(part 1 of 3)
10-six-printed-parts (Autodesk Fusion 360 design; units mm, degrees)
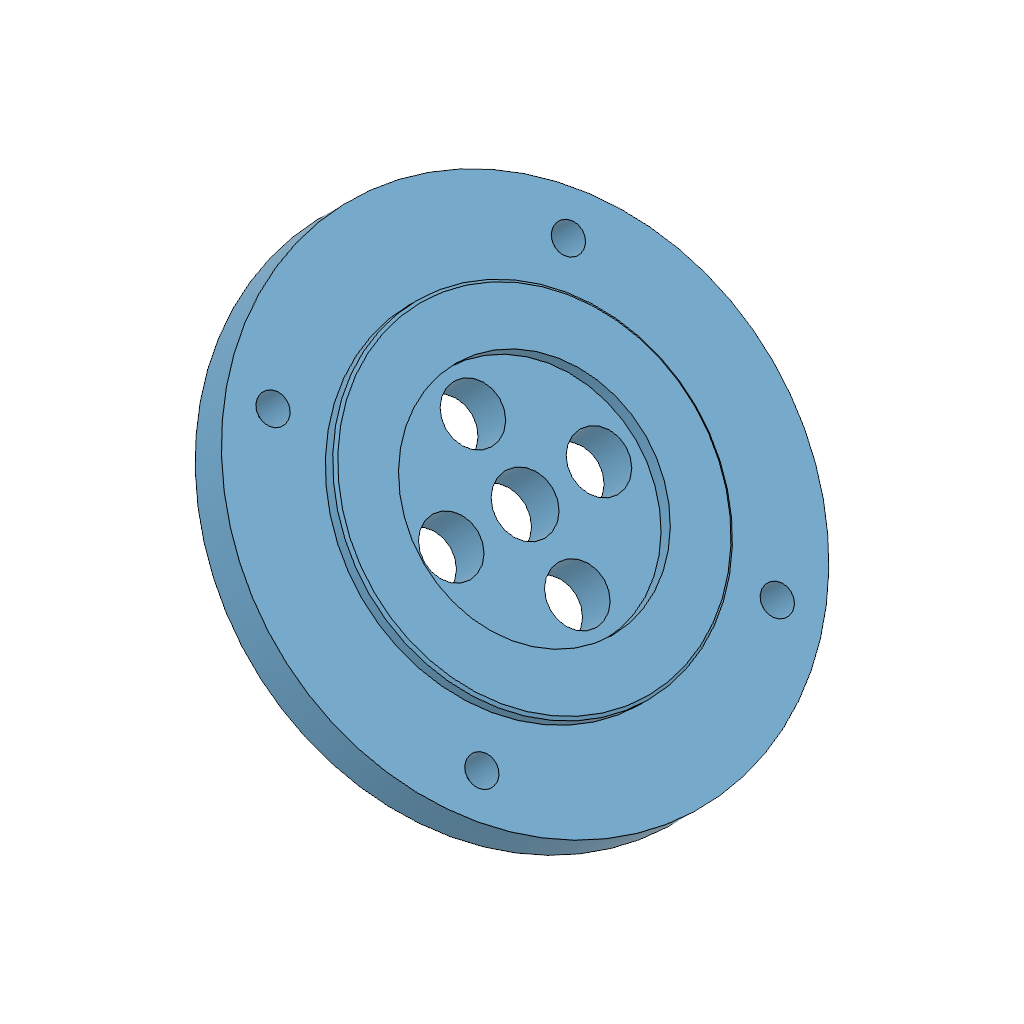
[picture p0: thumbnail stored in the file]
part number: 2026-11-02-20-17-55-344
part number: 2026-11-02-20-17-59-218
part number: 2026-11-02-20-17-59-224
part number: 2026-11-02-20-19-00-695
part number: 2026-11-02-20-19-03-009
part number: 2026-11-02-20-19-04-949
part number: 2026-11-02-20-19-06-912
parameter "bodyWidth" = 150 comment "Regular octagon across flats; corner diameter is larger."
parameter "bodyLength" = 260 comment "Overall straight length of the shared master blank."
parameter "splitAngle" = 45 comment "Keep this lesson angle at45 degrees."
parameter "faceGap" = 1 comment "Gap between the two printed joint faces."
parameter "wall" = 4.5 comment "Integrated shell and side brace radial thickness."
parameter "faceHalfWidth" = 31.066 (= "bodyWidth * ( sqrt(2) - 1 ) / 2") comment "Half-width of each outer planar facet."
parameter "memberWidth" = 8 comment "Nominal brace and corner chord width in a facet."
parameter "nodeHalfWidth" = 27.066 (= "faceHalfWidth - memberWidth / 2") comment "Chord centerlines measured from facet center."
parameter "jointNodeQ" = 7 comment "First truss skeleton row from the center joint plane."
parameter "endRim" = 10 comment "Uncut axial rim at each distant end."
parameter "endNodeX" = 124 (= "bodyLength / 2 - endRim + memberWidth / 2") comment "Last skeleton row before aperture inset."
parameter "apertureRadius" = 1.5 comment "Rounded internal corners at triangular openings."
parameter "spokeWidth" = 10 comment "Width of each deep bearing bulkhead spoke."
parameter "spokeDepth" = 18 comment "Bulkhead depth normal to the diagonal joint face."
parameter "carrierOD" = 52 comment "Outside of integrated A front bearing carrier."
parameter "rearCarrierClearance" = 46 comment "Internal carrier relief above front bearing shoulder."
parameter "tubeCornerChamfer" = 0.5 comment "Exposed outside octagon corner bevel."
parameter "tubeRimChamfer" = 0.3 comment "End rim and print-contact edge relief."
parameter "cordStation" = 125 (= "bodyLength / 2 - endRim / 2") comment "Load-test cord port center measured along body X."
parameter "bearingOD" = 22 comment "608 measured outside diameter."
parameter "bearingID" = 8 comment "608 bore."
parameter "bearingWidth" = 7 comment "608 width."
parameter "seatAllowance" = 0.2 comment "Trial DIAMETRAL clearance; choose with printed coupon."
parameter "seatDiameter" = 22.2 (= "bearingOD + seatAllowance") comment "Measured fit controls this."
parameter "coreOD" = 44 comment "Bearing holder outer diameter."
parameter "raceRelief" = 19.5 comment "Outer-ring shoulder opening; verify seals."
parameter "frontSeatDepth" = 7.1 comment "0.1 mm outer-ring axial allowance."
parameter "rearSeatDepth" = 7.2 comment "0.2 mm outer-ring axial float."
parameter "shoulder" = 3 comment "Backing behind each bearing seat."
parameter "supportSpacer" = 12 comment "Purchased metal M3 spacer length."
parameter "supportCircle" = 34 comment "Three M3 support bolts."
parameter "supportSpacerOD" = 6 comment "Purchased spacer outside diameter."
parameter "capThickness" = 3 comment "Both printed outer-ring retaining caps."
parameter "m3Clearance" = 3.3 comment "M3 through holes."
parameter "m4Clearance" = 4.3 comment "M4 through holes."
parameter "qFront" = 0.5 (= "faceGap / 2") comment "Front bearing starts at A mating face."
parameter "qFrontBack" = 10.6 (= "qFront + frontSeatDepth + shoulder") comment "End of integrated A holder."
parameter "qRearBase" = 22.6 (= "qFrontBack + supportSpacer") comment "Start of removable rear holder."
parameter "qRearBearing" = 25.6 (= "qRearBase + shoulder") comment "Rear bearing inner end."
parameter "qRearEnd" = 32.8 (= "qRearBearing + rearSeatDepth") comment "Rear holder outer end."
parameter "bearingSpacing" = 25.1 (= "qRearBearing - qFront") comment "Derived support-center spacing, not a bearing rating."
parameter "mountOD" = 76 comment "B mount and F flange outside diameter."
parameter "mountCircle" = 64 comment "Four M4 attachment holes."
parameter "mountOpening" = 50.3 comment "B through opening."
parameter "hubFace" = -23 comment "Metal hub flat mounting face."
parameter "adapterThickness" = 6 comment "F flange and metal compression sleeve length."
parameter "pilotDiameter" = 50 comment "F shallow centering pilot."
parameter "pilotInside" = 34 comment "Clearance around metal hub."
parameter "pilotHeight" = 2 comment "Short pilot only."
parameter "hubHoleSpacing" = 16 comment "Metal Sonic hub square hole spacing."
parameter "sleeveOD" = 8 comment "M4 metal compression sleeves."
parameter "sleeveAllowance" = 0.2 comment "Trial DIAMETRAL sleeve clearance."
parameter "shaftClearance" = 8.5 comment "F clearance hole; not a bearing."
parameter "nutAF" = 7.2 comment "M4 nominal 7 AF nut trial pocket."
parameter "nutDepth" = 4 comment "Open front M4 nut pocket."
parameter "rootRadius" = 1 comment "Hub-to-wall blend."
parameter "entryChamfer" = 0.4 comment "Assembly lead-in."
parameter "bedRelief" = 0.3 comment "Bed-contact edge allowance."
sketch "01 Master Octagon" plane through (0, 0, 0) normal (1, 0, 0) x axis (0, 0, -1)
  line L1 (31.066, 75) -> (75, 31.066)
  line L2 (-31.066, 75) -> (31.066, 75)
  line L3 (-75, 31.066) -> (-31.066, 75)
  line L4 (-75, -31.066) -> (-75, 31.066)
  line L5 (-31.066, -75) -> (-75, -31.066)
  line L6 (31.066, -75) -> (-31.066, -75)
  line L7 (75, -31.066) -> (31.066, -75)
  line L8 (75, 31.066) -> (75, -31.066)
  point P1 (0, 0)
  point P10 (0, 0)
  point P3 (31.066, 75)
  point P8 (31.066, -75)
  coincident P1 P10
  horizontal L2
  dimension "d59" distance P3 P8 = 150 (= "bodyWidth")
extrude "Extrude1" new body sketch "01 Master Octagon" distance 260 (= "bodyLength")
work_plane "WorkPlane1" RotateAngle 45 (= "splitAngle") ExtraOffset 0
split "Split1"
offset_faces "OffsetFaces1" distance -0.5 (= "-faceGap / 2")
offset_faces "OffsetFaces2" distance -0.5 (= "-faceGap / 2")
component_from_bodies "Body->Comp1"
component_from_bodies "Body->Comp2"
shell "Shell1" innerThickness 4.5 (= "wall")
shell "Shell1" innerThickness 4.5 (= "wall")
work_plane "WorkPlane1" RotateAngle -90 ExtraOffset 0
work_plane "WorkPlane2" AlongDistance 75 (= "bodyWidth / 2") ExtraOffset 0
sketch "A Facet 0 Triangle 1" plane through (0, 75, 0) normal (0, 1, 0) x axis (1, 0, 0)
  line L1 (-65.1005, -27.066) -> (-65.1005, 27.066)
  line L2 (60.9665, 27.066) -> (-65.1005, -27.066)
  line L3 (-65.1005, 27.066) -> (60.9665, 27.066)
  line L4 (-61.1005, -20.9953) -> (-61.1005, 23.066)
  line L5 (41.513, 23.066) -> (-61.1005, -20.9953)
  line L6 (-61.1005, 23.066) -> (41.513, 23.066)
  point P1 (0, 0)
  point P2 (-65.1005, 27.066)
  point P3 (-65.1005, -27.066)
  point P4 (60.9665, 27.066)
  dimension "d72" distance P1 P2 = 65.1005 (= "Linear Dimension-2")
  dimension "d73" distance P1 P2 = 27.066 (= "Linear Dimension-3")
  dimension "d74" distance P1 P3 = 65.1005 (= "Linear Dimension-4")
  dimension "d75" distance P1 P3 = 27.066 (= "Linear Dimension-5")
  dimension "d76" distance P1 P4 = 60.9665 (= "Linear Dimension-6")
  dimension "d77" distance P1 P4 = 27.066 (= "Linear Dimension-7")
  dimension "d78" = -4 (= "-memberWidth / 2")
extrude "Extrude1" cut sketch "A Facet 0 Triangle 1" profile of L5 L6 L4 against normal blind 4.7 (magnitude of "-( wall + 0.2 mm )")
sketch "A Facet 0 Triangle 2" plane through (0, 75, 0) normal (0, 1, 0) x axis (1, 0, 0)
  line L1 (60.9665, 27.066) -> (-65.1005, -27.066)
  line L2 (92.4832, -27.066) -> (60.9665, 27.066)
  line L3 (-65.1005, -27.066) -> (92.4832, -27.066)
  line L4 (59.2912, 21.9935) -> (-45.647, -23.066)
  line L5 (85.5258, -23.066) -> (59.2912, 21.9935)
  line L6 (-45.647, -23.066) -> (85.5258, -23.066)
  point P1 (0, 0)
  point P2 (-65.1005, -27.066)
  point P3 (60.9665, 27.066)
  point P4 (92.4832, -27.066)
  dimension "d81" distance P1 P2 = 65.1005 (= "Linear Dimension-2")
  dimension "d82" distance P1 P2 = 27.066 (= "Linear Dimension-3")
  dimension "d83" distance P1 P3 = 60.9665 (= "Linear Dimension-4")
  dimension "d84" distance P1 P3 = 27.066 (= "Linear Dimension-5")
  dimension "d85" distance P1 P4 = 92.4832 (= "Linear Dimension-6")
  dimension "d86" distance P1 P4 = 27.066 (= "Linear Dimension-7")
  dimension "d87" = 4 (= "memberWidth / 2")
extrude "Extrude2" cut sketch "A Facet 0 Triangle 2" profile of L5 L6 L4 against normal blind 4.7 (magnitude of "-( wall + 0.2 mm )")
sketch "A Facet 0 Triangle 3" plane through (0, 75, 0) normal (0, 1, 0) x axis (1, 0, 0)
  line L1 (92.4832, -27.066) -> (60.9665, 27.066)
  line L2 (124, 27.066) -> (92.4832, -27.066)
  line L3 (60.9665, 27.066) -> (124, 27.066)
  line L4 (92.4832, -19.1161) -> (67.924, 23.066)
  line L5 (117.0425, 23.066) -> (92.4832, -19.1161)
  line L6 (67.924, 23.066) -> (117.0425, 23.066)
  point P1 (0, 0)
  point P2 (60.9665, 27.066)
  point P3 (92.4832, -27.066)
  point P4 (124, 27.066)
  dimension "d90" distance P1 P2 = 60.9665 (= "Linear Dimension-2")
  dimension "d91" distance P1 P2 = 27.066 (= "Linear Dimension-3")
  dimension "d92" distance P1 P3 = 92.4832 (= "Linear Dimension-4")
  dimension "d93" distance P1 P3 = 27.066 (= "Linear Dimension-5")
  dimension "d94" distance P1 P4 = 124 (= "Linear Dimension-6")
  dimension "d95" distance P1 P4 = 27.066 (= "Linear Dimension-7")
  dimension "d96" = -4 (= "-memberWidth / 2")
extrude "Extrude3" cut sketch "A Facet 0 Triangle 3" profile of L5 L6 L4 against normal blind 4.7 (magnitude of "-( wall + 0.2 mm )")
sketch "A Facet 0 Triangle 4" plane through (0, 75, 0) normal (0, 1, 0) x axis (1, 0, 0)
  line L1 (124, 27.066) -> (92.4832, -27.066)
  line L2 (124, -27.066) -> (124, 27.066)
  line L3 (92.4832, -27.066) -> (124, -27.066)
  line L4 (120, 12.2459) -> (99.4407, -23.066)
  line L5 (120, -23.066) -> (120, 12.2459)
  line L6 (99.4407, -23.066) -> (120, -23.066)
  point P1 (0, 0)
  point P2 (92.4832, -27.066)
  point P3 (124, 27.066)
  point P4 (124, -27.066)
  dimension "d99" distance P1 P2 = 92.4832 (= "Linear Dimension-2")
  dimension "d100" distance P1 P2 = 27.066 (= "Linear Dimension-3")
  dimension "d101" distance P1 P3 = 124 (= "Linear Dimension-4")
  dimension "d102" distance P1 P3 = 27.066 (= "Linear Dimension-5")
  dimension "d103" distance P1 P4 = 124 (= "Linear Dimension-6")
  dimension "d104" distance P1 P4 = 27.066 (= "Linear Dimension-7")
  dimension "d105" = 4 (= "memberWidth / 2")
extrude "Extrude4" cut sketch "A Facet 0 Triangle 4" profile of L5 L6 L4 against normal blind 4.7 (magnitude of "-( wall + 0.2 mm )")
fillet "Fillet1" radius 1.5 (= "apertureRadius")
work_plane "WorkPlane3" RotateAngle -45 ExtraOffset 0
work_plane "WorkPlane4" AlongDistance 75 (= "bodyWidth / 2") ExtraOffset 0
sketch "A Facet 45 Triangle 1" plane through (0, 53.033, 53.033) normal (0, 0.7071, 0.7071) x axis (1, 0, 0)
  line L1 (-23.9949, -27.066) -> (-62.2721, 27.066)
  line L2 (-0.1814, 27.066) -> (-23.9949, -27.066)
  line L3 (-62.2721, 27.066) -> (-0.1814, 27.066)
  line L4 (-24.81, -18.9852) -> (-54.5447, 23.066)
  line L5 (-6.311, 23.066) -> (-24.81, -18.9852)
  line L6 (-54.5447, 23.066) -> (-6.311, 23.066)
  point P1 (0, 0)
  point P2 (-62.2721, 27.066)
  point P3 (-23.9949, -27.066)
  point P4 (-0.1814, 27.066)
  dimension "d114" distance P1 P2 = 62.2721 (= "Linear Dimension-2")
  dimension "d115" distance P1 P2 = 27.066 (= "Linear Dimension-3")
  dimension "d116" distance P1 P3 = 23.9949 (= "Linear Dimension-4")
  dimension "d117" distance P1 P3 = 27.066 (= "Linear Dimension-5")
  dimension "d118" distance P1 P4 = 0.1814 (= "Linear Dimension-6")
  dimension "d119" distance P1 P4 = 27.066 (= "Linear Dimension-7")
  dimension "d120" = -4 (= "-memberWidth / 2")
extrude "Extrude5" cut sketch "A Facet 45 Triangle 1" profile of L5 L6 L4 against normal blind 4.7 (magnitude of "-( wall + 0.2 mm )")
sketch "A Facet 45 Triangle 2" plane through (0, 53.033, 53.033) normal (0, 0.7071, 0.7071) x axis (1, 0, 0)
  line L1 (-0.1814, 27.066) -> (-23.9949, -27.066)
  line L2 (74.6684, -27.066) -> (-0.1814, 27.066)
  line L3 (-23.9949, -27.066) -> (74.6684, -27.066)
  line L4 (1.4863, 20.9235) -> (-17.8653, -23.066)
  line L5 (62.3117, -23.066) -> (1.4863, 20.9235)
  line L6 (-17.8653, -23.066) -> (62.3117, -23.066)
  point P1 (0, 0)
  point P2 (-23.9949, -27.066)
  point P3 (-0.1814, 27.066)
  point P4 (74.6684, -27.066)
  dimension "d123" distance P1 P2 = 23.9949 (= "Linear Dimension-2")
  dimension "d124" distance P1 P2 = 27.066 (= "Linear Dimension-3")
  dimension "d125" distance P1 P3 = 0.1814 (= "Linear Dimension-4")
  dimension "d126" distance P1 P3 = 27.066 (= "Linear Dimension-5")
  dimension "d127" distance P1 P4 = 74.6684 (= "Linear Dimension-6")
  dimension "d128" distance P1 P4 = 27.066 (= "Linear Dimension-7")
  dimension "d129" = 4 (= "memberWidth / 2")
extrude "Extrude6" cut sketch "A Facet 45 Triangle 2" profile of L5 L6 L4 against normal blind 4.7 (magnitude of "-( wall + 0.2 mm )")
sketch "A Facet 45 Triangle 3" plane through (0, 53.033, 53.033) normal (0, 0.7071, 0.7071) x axis (1, 0, 0)
  line L1 (74.6684, -27.066) -> (-0.1814, 27.066)
  line L2 (124, 27.066) -> (74.6684, -27.066)
  line L3 (-0.1814, 27.066) -> (124, 27.066)
  line L4 (74.1179, -21.7315) -> (12.1753, 23.066)
  line L5 (114.9429, 23.066) -> (74.1179, -21.7315)
  line L6 (12.1753, 23.066) -> (114.9429, 23.066)
  point P1 (0, 0)
  point P2 (-0.1814, 27.066)
  point P3 (74.6684, -27.066)
  point P4 (124, 27.066)
  dimension "d132" distance P1 P2 = 0.1814 (= "Linear Dimension-2")
  dimension "d133" distance P1 P2 = 27.066 (= "Linear Dimension-3")
  dimension "d134" distance P1 P3 = 74.6684 (= "Linear Dimension-4")
  dimension "d135" distance P1 P3 = 27.066 (= "Linear Dimension-5")
  dimension "d136" distance P1 P4 = 124 (= "Linear Dimension-6")
  dimension "d137" distance P1 P4 = 27.066 (= "Linear Dimension-7")
  dimension "d138" = -4 (= "-memberWidth / 2")
extrude "Extrude7" cut sketch "A Facet 45 Triangle 3" profile of L5 L6 L4 against normal blind 4.7 (magnitude of "-( wall + 0.2 mm )")
sketch "A Facet 45 Triangle 4" plane through (0, 53.033, 53.033) normal (0, 0.7071, 0.7071) x axis (1, 0, 0)
  line L1 (124, 27.066) -> (74.6684, -27.066)
  line L2 (124, -27.066) -> (124, 27.066)
  line L3 (74.6684, -27.066) -> (124, -27.066)
  line L4 (120, 16.7383) -> (83.7255, -23.066)
  line L5 (120, -23.066) -> (120, 16.7383)
  line L6 (83.7255, -23.066) -> (120, -23.066)
  point P1 (0, 0)
  point P2 (74.6684, -27.066)
  point P3 (124, 27.066)
  point P4 (124, -27.066)
  dimension "d141" distance P1 P2 = 74.6684 (= "Linear Dimension-2")
  dimension "d142" distance P1 P2 = 27.066 (= "Linear Dimension-3")
  dimension "d143" distance P1 P3 = 124 (= "Linear Dimension-4")
  dimension "d144" distance P1 P3 = 27.066 (= "Linear Dimension-5")
  dimension "d145" distance P1 P4 = 124 (= "Linear Dimension-6")
  dimension "d146" distance P1 P4 = 27.066 (= "Linear Dimension-7")
  dimension "d147" = 4 (= "memberWidth / 2")
extrude "Extrude8" cut sketch "A Facet 45 Triangle 4" profile of L5 L6 L4 against normal blind 4.7 (magnitude of "-( wall + 0.2 mm )")
fillet "Fillet2" radius 1.5 (= "apertureRadius")
work_plane "WorkPlane5" RotateAngle 0 ExtraOffset 0
work_plane "WorkPlane6" AlongDistance 75 (= "bodyWidth / 2") ExtraOffset 0
sketch "A Facet 90 Triangle 1" plane through (0, 0, 75) normal (0, 0, 1) x axis (1, 0, 0)
  line L1 (36.9655, -27.066) -> (-17.1665, 27.066)
  line L2 (53.4167, 27.066) -> (36.9655, -27.066)
  line L3 (-17.1665, 27.066) -> (53.4167, 27.066)
  line L4 (35.0777, -19.5214) -> (-7.5097, 23.066)
  line L5 (48.0205, 23.066) -> (35.0777, -19.5214)
  line L6 (-7.5097, 23.066) -> (48.0205, 23.066)
  point P1 (0, 0)
  point P2 (-17.1665, 27.066)
  point P3 (36.9655, -27.066)
  point P4 (53.4167, 27.066)
  dimension "d156" distance P1 P2 = 17.1665 (= "Linear Dimension-2")
  dimension "d157" distance P1 P2 = 27.066 (= "Linear Dimension-3")
  dimension "d158" distance P1 P3 = 36.9655 (= "Linear Dimension-4")
  dimension "d159" distance P1 P3 = 27.066 (= "Linear Dimension-5")
  dimension "d160" distance P1 P4 = 53.4167 (= "Linear Dimension-6")
  dimension "d161" distance P1 P4 = 27.066 (= "Linear Dimension-7")
  dimension "d162" = -4 (= "-memberWidth / 2")
extrude "Extrude9" cut sketch "A Facet 90 Triangle 1" profile of L5 L6 L4 against normal blind 4.7 (magnitude of "-( wall + 0.2 mm )")
sketch "A Facet 90 Triangle 2" plane through (0, 0, 75) normal (0, 0, 1) x axis (1, 0, 0)
  line L1 (53.4167, 27.066) -> (36.9655, -27.066)
  line L2 (124, -27.066) -> (53.4167, 27.066)
  line L3 (36.9655, -27.066) -> (124, -27.066)
  line L4 (55.5648, 20.3777) -> (42.3618, -23.066)
  line L5 (112.2115, -23.066) -> (55.5648, 20.3777)
  line L6 (42.3618, -23.066) -> (112.2115, -23.066)
  point P1 (0, 0)
  point P2 (36.9655, -27.066)
  point P3 (53.4167, 27.066)
  point P4 (124, -27.066)
  dimension "d165" distance P1 P2 = 36.9655 (= "Linear Dimension-2")
  dimension "d166" distance P1 P2 = 27.066 (= "Linear Dimension-3")
  dimension "d167" distance P1 P3 = 53.4167 (= "Linear Dimension-4")
  dimension "d168" distance P1 P3 = 27.066 (= "Linear Dimension-5")
  dimension "d169" distance P1 P4 = 124 (= "Linear Dimension-6")
  dimension "d170" distance P1 P4 = 27.066 (= "Linear Dimension-7")
  dimension "d171" = 4 (= "memberWidth / 2")
extrude "Extrude10" cut sketch "A Facet 90 Triangle 2" profile of L5 L6 L4 against normal blind 4.7 (magnitude of "-( wall + 0.2 mm )")
sketch "A Facet 90 Triangle 3" plane through (0, 0, 75) normal (0, 0, 1) x axis (1, 0, 0)
  line L1 (124, -27.066) -> (53.4167, 27.066)
  line L2 (124, 27.066) -> (124, -27.066)
  line L3 (53.4167, 27.066) -> (124, 27.066)
  line L4 (120, -18.9574) -> (65.2053, 23.066)
  line L5 (120, 23.066) -> (120, -18.9574)
  line L6 (65.2053, 23.066) -> (120, 23.066)
  point P1 (0, 0)
  point P2 (53.4167, 27.066)
  point P3 (124, -27.066)
  point P4 (124, 27.066)
  dimension "d174" distance P1 P2 = 53.4167 (= "Linear Dimension-2")
  dimension "d175" distance P1 P2 = 27.066 (= "Linear Dimension-3")
  dimension "d176" distance P1 P3 = 124 (= "Linear Dimension-4")
  dimension "d177" distance P1 P3 = 27.066 (= "Linear Dimension-5")
  dimension "d178" distance P1 P4 = 124 (= "Linear Dimension-6")
  dimension "d179" distance P1 P4 = 27.066 (= "Linear Dimension-7")
  dimension "d180" = -4 (= "-memberWidth / 2")
extrude "Extrude11" cut sketch "A Facet 90 Triangle 3" profile of L5 L6 L4 against normal blind 4.7 (magnitude of "-( wall + 0.2 mm )")
fillet "Fillet3" radius 1.5 (= "apertureRadius")
work_plane "WorkPlane7" RotateAngle 45 ExtraOffset 0
work_plane "WorkPlane8" AlongDistance 75 (= "bodyWidth / 2") ExtraOffset 0
sketch "A Facet 135 Triangle 1" plane through (0, -53.033, 53.033) normal (0, -0.7071, 0.7071) x axis (1, 0, 0)
  line L1 (82.0711, -27.066) -> (43.7939, 27.066)
  line L2 (124, 27.066) -> (82.0711, -27.066)
  line L3 (43.7939, 27.066) -> (124, 27.066)
  line L4 (82.2175, -20.3449) -> (51.5213, 23.066)
  line L5 (115.8422, 23.066) -> (82.2175, -20.3449)
  line L6 (51.5213, 23.066) -> (115.8422, 23.066)
  point P1 (0, 0)
  point P2 (43.7939, 27.066)
  point P3 (82.0711, -27.066)
  point P4 (124, 27.066)
  dimension "d189" distance P1 P2 = 43.7939 (= "Linear Dimension-2")
  dimension "d190" distance P1 P2 = 27.066 (= "Linear Dimension-3")
  dimension "d191" distance P1 P3 = 82.0711 (= "Linear Dimension-4")
  dimension "d192" distance P1 P3 = 27.066 (= "Linear Dimension-5")
  dimension "d193" distance P1 P4 = 124 (= "Linear Dimension-6")
  dimension "d194" distance P1 P4 = 27.066 (= "Linear Dimension-7")
  dimension "d195" = -4 (= "-memberWidth / 2")
extrude "Extrude12" cut sketch "A Facet 135 Triangle 1" profile of L5 L6 L4 against normal blind 4.7 (magnitude of "-( wall + 0.2 mm )")
sketch "A Facet 135 Triangle 2" plane through (0, -53.033, 53.033) normal (0, -0.7071, 0.7071) x axis (1, 0, 0)
  line L1 (124, 27.066) -> (82.0711, -27.066)
  line L2 (124, -27.066) -> (124, 27.066)
  line L3 (82.0711, -27.066) -> (124, -27.066)
  line L4 (120, 15.3697) -> (90.2289, -23.066)
  line L5 (120, -23.066) -> (120, 15.3697)
  line L6 (90.2289, -23.066) -> (120, -23.066)
  point P1 (0, 0)
  point P2 (82.0711, -27.066)
  point P3 (124, 27.066)
  point P4 (124, -27.066)
  dimension "d198" distance P1 P2 = 82.0711 (= "Linear Dimension-2")
  dimension "d199" distance P1 P2 = 27.066 (= "Linear Dimension-3")
  dimension "d200" distance P1 P3 = 124 (= "Linear Dimension-4")
  dimension "d201" distance P1 P3 = 27.066 (= "Linear Dimension-5")
  dimension "d202" distance P1 P4 = 124 (= "Linear Dimension-6")
  dimension "d203" distance P1 P4 = 27.066 (= "Linear Dimension-7")
  dimension "d204" = 4 (= "memberWidth / 2")
extrude "Extrude13" cut sketch "A Facet 135 Triangle 2" profile of L5 L6 L4 against normal blind 4.7 (magnitude of "-( wall + 0.2 mm )")
fillet "Fillet4" radius 1.5 (= "apertureRadius")
work_plane "WorkPlane9" RotateAngle 90 ExtraOffset 0
work_plane "WorkPlane10" AlongDistance 75 (= "bodyWidth / 2") ExtraOffset 0
sketch "A Facet 180 Triangle 1" plane through (0, -75, 0) normal (0, -1, 0) x axis (-1, 0, 0)
  line L1 (-84.8995, 27.066) -> (-84.8995, -27.066)
  line L2 (-124, -27.066) -> (-84.8995, 27.066)
  line L3 (-84.8995, -27.066) -> (-124, -27.066)
  line L4 (-88.8995, 14.697) -> (-88.8995, -23.066)
  line L5 (-116.1764, -23.066) -> (-88.8995, 14.697)
  line L6 (-88.8995, -23.066) -> (-116.1764, -23.066)
  point P1 (0, 0)
  point P2 (-84.8995, -27.066)
  point P3 (-84.8995, 27.066)
  point P4 (-124, -27.066)
  dimension "d213" distance P1 P2 = 84.8995 (= "Linear Dimension-2")
  dimension "d214" distance P1 P2 = 27.066 (= "Linear Dimension-3")
  dimension "d215" distance P1 P3 = 84.8995 (= "Linear Dimension-4")
  dimension "d216" distance P1 P3 = 27.066 (= "Linear Dimension-5")
  dimension "d217" distance P1 P4 = 124 (= "Linear Dimension-6")
  dimension "d218" distance P1 P4 = 27.066 (= "Linear Dimension-7")
  dimension "d219" = -4 (= "-memberWidth / 2")
extrude "Extrude14" cut sketch "A Facet 180 Triangle 1" profile of L5 L6 L4 against normal blind 4.7 (magnitude of "-( wall + 0.2 mm )")
sketch "A Facet 180 Triangle 2" plane through (0, -75, 0) normal (0, -1, 0) x axis (-1, 0, 0)
  line L1 (-124, -27.066) -> (-84.8995, 27.066)
  line L2 (-124, 27.066) -> (-124, -27.066)
  line L3 (-84.8995, 27.066) -> (-124, 27.066)
  line L4 (-120, -14.697) -> (-92.7231, 23.066)
  line L5 (-120, 23.066) -> (-120, -14.697)
  line L6 (-92.7231, 23.066) -> (-120, 23.066)
  point P1 (0, 0)
  point P2 (-84.8995, 27.066)
  point P3 (-124, -27.066)
  point P4 (-124, 27.066)
  dimension "d222" distance P1 P2 = 84.8995 (= "Linear Dimension-2")
  dimension "d223" distance P1 P2 = 27.066 (= "Linear Dimension-3")
  dimension "d224" distance P1 P3 = 124 (= "Linear Dimension-4")
  dimension "d225" distance P1 P3 = 27.066 (= "Linear Dimension-5")
  dimension "d226" distance P1 P4 = 124 (= "Linear Dimension-6")
  dimension "d227" distance P1 P4 = 27.066 (= "Linear Dimension-7")
  dimension "d228" = 4 (= "memberWidth / 2")
extrude "Extrude15" cut sketch "A Facet 180 Triangle 2" profile of L5 L6 L4 against normal blind 4.7 (magnitude of "-( wall + 0.2 mm )")
fillet "Fillet5" radius 1.5 (= "apertureRadius")
work_plane "WorkPlane11" RotateAngle 135 ExtraOffset 0
work_plane "WorkPlane12" AlongDistance 75 (= "bodyWidth / 2") ExtraOffset 0
sketch "A Facet 225 Triangle 1" plane through (0, -53.033, -53.033) normal (0, -0.7071, -0.7071) x axis (1, 0, 0)
  line L1 (43.7939, -27.066) -> (82.0711, 27.066)
  line L2 (124, 27.066) -> (43.7939, -27.066)
  line L3 (82.0711, 27.066) -> (124, 27.066)
  line L4 (59.6927, -11.51) -> (84.1416, 23.066)
  line L5 (110.9231, 23.066) -> (59.6927, -11.51)
  line L6 (84.1416, 23.066) -> (110.9231, 23.066)
  point P1 (0, 0)
  point P2 (82.0711, 27.066)
  point P3 (43.7939, -27.066)
  point P4 (124, 27.066)
  dimension "d237" distance P1 P2 = 82.0711 (= "Linear Dimension-2")
  dimension "d238" distance P1 P2 = 27.066 (= "Linear Dimension-3")
  dimension "d239" distance P1 P3 = 43.7939 (= "Linear Dimension-4")
  dimension "d240" distance P1 P3 = 27.066 (= "Linear Dimension-5")
  dimension "d241" distance P1 P4 = 124 (= "Linear Dimension-6")
  dimension "d242" distance P1 P4 = 27.066 (= "Linear Dimension-7")
  dimension "d243" = -4 (= "-memberWidth / 2")
extrude "Extrude16" cut sketch "A Facet 225 Triangle 1" profile of L5 L6 L4 against normal blind 4.7 (magnitude of "-( wall + 0.2 mm )")
sketch "A Facet 225 Triangle 2" plane through (0, -53.033, -53.033) normal (0, -0.7071, -0.7071) x axis (1, 0, 0)
  line L1 (124, 27.066) -> (43.7939, -27.066)
  line L2 (124, -27.066) -> (124, 27.066)
  line L3 (43.7939, -27.066) -> (124, -27.066)
  line L4 (120, 19.5406) -> (56.8709, -23.066)
  line L5 (120, -23.066) -> (120, 19.5406)
  line L6 (56.8709, -23.066) -> (120, -23.066)
  point P1 (0, 0)
  point P2 (43.7939, -27.066)
  point P3 (124, 27.066)
  point P4 (124, -27.066)
  dimension "d246" distance P1 P2 = 43.7939 (= "Linear Dimension-2")
  dimension "d247" distance P1 P2 = 27.066 (= "Linear Dimension-3")
  dimension "d248" distance P1 P3 = 124 (= "Linear Dimension-4")
  dimension "d249" distance P1 P3 = 27.066 (= "Linear Dimension-5")
  dimension "d250" distance P1 P4 = 124 (= "Linear Dimension-6")
  dimension "d251" distance P1 P4 = 27.066 (= "Linear Dimension-7")
  dimension "d252" = 4 (= "memberWidth / 2")
extrude "Extrude17" cut sketch "A Facet 225 Triangle 2" profile of L5 L6 L4 against normal blind 4.7 (magnitude of "-( wall + 0.2 mm )")
fillet "Fillet6" radius 1.5 (= "apertureRadius")
work_plane "WorkPlane13" RotateAngle 180 ExtraOffset 0
work_plane "WorkPlane14" AlongDistance 75 (= "bodyWidth / 2") ExtraOffset 0
sketch "A Facet 270 Triangle 1" plane through (0, 0, -75) normal (0, 0, -1) x axis (-1, 0, 0)
  line L1 (17.1665, 27.066) -> (-36.9655, -27.066)
  line L2 (-80.4828, -27.066) -> (17.1665, 27.066)
  line L3 (-36.9655, -27.066) -> (-80.4828, -27.066)
  line L4 (-5.7896, 9.7668) -> (-38.6224, -23.066)
  line L5 (-65.0169, -23.066) -> (-5.7896, 9.7668)
  line L6 (-38.6224, -23.066) -> (-65.0169, -23.066)
  point P1 (0, 0)
  point P2 (-36.9655, -27.066)
  point P3 (17.1665, 27.066)
  point P4 (-80.4828, -27.066)
  dimension "d261" distance P1 P2 = 36.9655 (= "Linear Dimension-2")
  dimension "d262" distance P1 P2 = 27.066 (= "Linear Dimension-3")
  dimension "d263" distance P1 P3 = 17.1665 (= "Linear Dimension-4")
  dimension "d264" distance P1 P3 = 27.066 (= "Linear Dimension-5")
  dimension "d265" distance P1 P4 = 80.4828 (= "Linear Dimension-6")
  dimension "d266" distance P1 P4 = 27.066 (= "Linear Dimension-7")
  dimension "d267" = -4 (= "-memberWidth / 2")
extrude "Extrude18" cut sketch "A Facet 270 Triangle 1" profile of L5 L6 L4 against normal blind 4.7 (magnitude of "-( wall + 0.2 mm )")
sketch "A Facet 270 Triangle 2" plane through (0, 0, -75) normal (0, 0, -1) x axis (-1, 0, 0)
  line L1 (-80.4828, -27.066) -> (17.1665, 27.066)
  line L2 (-124, 27.066) -> (-80.4828, -27.066)
  line L3 (17.1665, 27.066) -> (-124, 27.066)
  line L4 (-79.4759, -21.9343) -> (1.7007, 23.066)
  line L5 (-115.6521, 23.066) -> (-79.4759, -21.9343)
  line L6 (1.7007, 23.066) -> (-115.6521, 23.066)
  point P1 (0, 0)
  point P2 (17.1665, 27.066)
  point P3 (-80.4828, -27.066)
  point P4 (-124, 27.066)
  dimension "d270" distance P1 P2 = 17.1665 (= "Linear Dimension-2")
  dimension "d271" distance P1 P2 = 27.066 (= "Linear Dimension-3")
  dimension "d272" distance P1 P3 = 80.4828 (= "Linear Dimension-4")
  dimension "d273" distance P1 P3 = 27.066 (= "Linear Dimension-5")
  dimension "d274" distance P1 P4 = 124 (= "Linear Dimension-6")
  dimension "d275" distance P1 P4 = 27.066 (= "Linear Dimension-7")
  dimension "d276" = 4 (= "memberWidth / 2")
extrude "Extrude19" cut sketch "A Facet 270 Triangle 2" profile of L5 L6 L4 against normal blind 4.7 (magnitude of "-( wall + 0.2 mm )")
sketch "A Facet 270 Triangle 3" plane through (0, 0, -75) normal (0, 0, -1) x axis (-1, 0, 0)
  line L1 (-124, 27.066) -> (-80.4828, -27.066)
  line L2 (-124, -27.066) -> (-124, 27.066)
  line L3 (-80.4828, -27.066) -> (-124, -27.066)
  line L4 (-120, 15.7062) -> (-88.8307, -23.066)
  line L5 (-120, -23.066) -> (-120, 15.7062)
  line L6 (-88.8307, -23.066) -> (-120, -23.066)
  point P1 (0, 0)
  point P2 (-80.4828, -27.066)
  point P3 (-124, 27.066)
  point P4 (-124, -27.066)
  dimension "d279" distance P1 P2 = 80.4828 (= "Linear Dimension-2")
  dimension "d280" distance P1 P2 = 27.066 (= "Linear Dimension-3")
  dimension "d281" distance P1 P3 = 124 (= "Linear Dimension-4")
  dimension "d282" distance P1 P3 = 27.066 (= "Linear Dimension-5")
  dimension "d283" distance P1 P4 = 124 (= "Linear Dimension-6")
  dimension "d284" distance P1 P4 = 27.066 (= "Linear Dimension-7")
  dimension "d285" = -4 (= "-memberWidth / 2")
extrude "Extrude20" cut sketch "A Facet 270 Triangle 3" profile of L5 L6 L4 against normal blind 4.7 (magnitude of "-( wall + 0.2 mm )")
fillet "Fillet7" radius 1.5 (= "apertureRadius")
work_plane "WorkPlane15" RotateAngle 225 ExtraOffset 0
work_plane "WorkPlane16" AlongDistance 75 (= "bodyWidth / 2") ExtraOffset 0
sketch "A Facet 315 Triangle 1" plane through (0, 53.033, -53.033) normal (0, 0.7071, -0.7071) x axis (1, 0, 0)
  line L1 (-62.2721, -27.066) -> (-23.9949, 27.066)
  line L2 (25.3367, 27.066) -> (-62.2721, -27.066)
  line L3 (-23.9949, 27.066) -> (25.3367, 27.066)
  line L4 (-47.6674, -13.34) -> (-21.9244, 23.066)
  line L5 (11.2532, 23.066) -> (-47.6674, -13.34)
  line L6 (-21.9244, 23.066) -> (11.2532, 23.066)
  point P1 (0, 0)
  point P2 (-23.9949, 27.066)
  point P3 (-62.2721, -27.066)
  point P4 (25.3367, 27.066)
  dimension "d294" distance P1 P2 = 23.9949 (= "Linear Dimension-2")
  dimension "d295" distance P1 P2 = 27.066 (= "Linear Dimension-3")
  dimension "d296" distance P1 P3 = 62.2721 (= "Linear Dimension-4")
  dimension "d297" distance P1 P3 = 27.066 (= "Linear Dimension-5")
  dimension "d298" distance P1 P4 = 25.3367 (= "Linear Dimension-6")
  dimension "d299" distance P1 P4 = 27.066 (= "Linear Dimension-7")
  dimension "d300" = -4 (= "-memberWidth / 2")
extrude "Extrude21" cut sketch "A Facet 315 Triangle 1" profile of L5 L6 L4 against normal blind 4.7 (magnitude of "-( wall + 0.2 mm )")
sketch "A Facet 315 Triangle 2" plane through (0, 53.033, -53.033) normal (0, 0.7071, -0.7071) x axis (1, 0, 0)
  line L1 (25.3367, 27.066) -> (-62.2721, -27.066)
  line L2 (61.9093, -27.066) -> (25.3367, 27.066)
  line L3 (-62.2721, -27.066) -> (61.9093, -27.066)
  line L4 (24.1722, 21.6445) -> (-48.1886, -23.066)
  line L5 (54.3795, -23.066) -> (24.1722, 21.6445)
  line L6 (-48.1886, -23.066) -> (54.3795, -23.066)
  point P1 (0, 0)
  point P2 (-62.2721, -27.066)
  point P3 (25.3367, 27.066)
  point P4 (61.9093, -27.066)
  dimension "d303" distance P1 P2 = 62.2721 (= "Linear Dimension-2")
  dimension "d304" distance P1 P2 = 27.066 (= "Linear Dimension-3")
  dimension "d305" distance P1 P3 = 25.3367 (= "Linear Dimension-4")
  dimension "d306" distance P1 P3 = 27.066 (= "Linear Dimension-5")
  dimension "d307" distance P1 P4 = 61.9093 (= "Linear Dimension-6")
  dimension "d308" distance P1 P4 = 27.066 (= "Linear Dimension-7")
  dimension "d309" = 4 (= "memberWidth / 2")
extrude "Extrude22" cut sketch "A Facet 315 Triangle 2" profile of L5 L6 L4 against normal blind 4.7 (magnitude of "-( wall + 0.2 mm )")
sketch "A Facet 315 Triangle 3" plane through (0, 53.033, -53.033) normal (0, 0.7071, -0.7071) x axis (1, 0, 0)
  line L1 (61.9093, -27.066) -> (25.3367, 27.066)
  line L2 (124, 27.066) -> (61.9093, -27.066)
  line L3 (25.3367, 27.066) -> (124, 27.066)
  line L4 (62.6909, -21.0779) -> (32.8665, 23.066)
  line L5 (113.325, 23.066) -> (62.6909, -21.0779)
  line L6 (32.8665, 23.066) -> (113.325, 23.066)
  point P1 (0, 0)
  point P2 (25.3367, 27.066)
  point P3 (61.9093, -27.066)
  point P4 (124, 27.066)
  dimension "d312" distance P1 P2 = 25.3367 (= "Linear Dimension-2")
  dimension "d313" distance P1 P2 = 27.066 (= "Linear Dimension-3")
  dimension "d314" distance P1 P3 = 61.9093 (= "Linear Dimension-4")
  dimension "d315" distance P1 P3 = 27.066 (= "Linear Dimension-5")
  dimension "d316" distance P1 P4 = 124 (= "Linear Dimension-6")
  dimension "d317" distance P1 P4 = 27.066 (= "Linear Dimension-7")
  dimension "d318" = -4 (= "-memberWidth / 2")
extrude "Extrude23" cut sketch "A Facet 315 Triangle 3" profile of L5 L6 L4 against normal blind 4.7 (magnitude of "-( wall + 0.2 mm )")
sketch "A Facet 315 Triangle 4" plane through (0, 53.033, -53.033) normal (0, 0.7071, -0.7071) x axis (1, 0, 0)
  line L1 (124, 27.066) -> (61.9093, -27.066)
  line L2 (124, -27.066) -> (124, 27.066)
  line L3 (61.9093, -27.066) -> (124, -27.066)
  line L4 (120, 18.272) -> (72.5843, -23.066)
  line L5 (120, -23.066) -> (120, 18.272)
  line L6 (72.5843, -23.066) -> (120, -23.066)
  point P1 (0, 0)
  point P2 (61.9093, -27.066)
  point P3 (124, 27.066)
  point P4 (124, -27.066)
  dimension "d321" distance P1 P2 = 61.9093 (= "Linear Dimension-2")
  dimension "d322" distance P1 P2 = 27.066 (= "Linear Dimension-3")
  dimension "d323" distance P1 P3 = 124 (= "Linear Dimension-4")
  dimension "d324" distance P1 P3 = 27.066 (= "Linear Dimension-5")
  dimension "d325" distance P1 P4 = 124 (= "Linear Dimension-6")
  dimension "d326" distance P1 P4 = 27.066 (= "Linear Dimension-7")
  dimension "d327" = 4 (= "memberWidth / 2")
extrude "Extrude24" cut sketch "A Facet 315 Triangle 4" profile of L5 L6 L4 against normal blind 4.7 (magnitude of "-( wall + 0.2 mm )")
fillet "Fillet8" radius 1.5 (= "apertureRadius")
work_plane "WorkPlane1" RotateAngle -90 ExtraOffset 0
work_plane "WorkPlane2" AlongDistance 75 (= "bodyWidth / 2") ExtraOffset 0
sketch "B Facet 0 Triangle 1" plane through (0, 75, 0) normal (0, 1, 0) x axis (1, 0, 0)
  line L1 (-84.8995, -27.066) -> (-84.8995, 27.066)
  line L2 (-124, 27.066) -> (-84.8995, -27.066)
  line L3 (-84.8995, 27.066) -> (-124, 27.066)
  line L4 (-88.8995, -14.697) -> (-88.8995, 23.066)
  line L5 (-116.1764, 23.066) -> (-88.8995, -14.697)
  line L6 (-88.8995, 23.066) -> (-116.1764, 23.066)
  point P1 (0, 0)
  point P2 (-84.8995, 27.066)
  point P3 (-84.8995, -27.066)
  point P4 (-124, 27.066)
  dimension "d336" distance P1 P2 = 84.8995 (= "Linear Dimension-2")
  dimension "d337" distance P1 P2 = 27.066 (= "Linear Dimension-3")
  dimension "d338" distance P1 P3 = 84.8995 (= "Linear Dimension-4")
  dimension "d339" distance P1 P3 = 27.066 (= "Linear Dimension-5")
  dimension "d340" distance P1 P4 = 124 (= "Linear Dimension-6")
  dimension "d341" distance P1 P4 = 27.066 (= "Linear Dimension-7")
  dimension "d342" = 4 (= "memberWidth / 2")
extrude "Extrude1" cut sketch "B Facet 0 Triangle 1" profile of L5 L6 L4 against normal blind 4.7 (magnitude of "-( wall + 0.2 mm )")
sketch "B Facet 0 Triangle 2" plane through (0, 75, 0) normal (0, 1, 0) x axis (1, 0, 0)
  line L1 (-124, 27.066) -> (-84.8995, -27.066)
  line L2 (-124, -27.066) -> (-124, 27.066)
  line L3 (-84.8995, -27.066) -> (-124, -27.066)
  line L4 (-120, 14.697) -> (-92.7231, -23.066)
  line L5 (-120, -23.066) -> (-120, 14.697)
  line L6 (-92.7231, -23.066) -> (-120, -23.066)
  point P1 (0, 0)
  point P2 (-84.8995, -27.066)
  point P3 (-124, 27.066)
  point P4 (-124, -27.066)
  dimension "d345" distance P1 P2 = 84.8995 (= "Linear Dimension-2")
  dimension "d346" distance P1 P2 = 27.066 (= "Linear Dimension-3")
  dimension "d347" distance P1 P3 = 124 (= "Linear Dimension-4")
  dimension "d348" distance P1 P3 = 27.066 (= "Linear Dimension-5")
  dimension "d349" distance P1 P4 = 124 (= "Linear Dimension-6")
  dimension "d350" distance P1 P4 = 27.066 (= "Linear Dimension-7")
  dimension "d351" = -4 (= "-memberWidth / 2")
extrude "Extrude2" cut sketch "B Facet 0 Triangle 2" profile of L5 L6 L4 against normal blind 4.7 (magnitude of "-( wall + 0.2 mm )")
fillet "Fillet1" radius 1.5 (= "apertureRadius")
work_plane "WorkPlane3" RotateAngle -45 ExtraOffset 0
work_plane "WorkPlane4" AlongDistance 75 (= "bodyWidth / 2") ExtraOffset 0
sketch "B Facet 45 Triangle 1" plane through (0, 53.033, 53.033) normal (0, 0.7071, 0.7071) x axis (1, 0, 0)
  line L1 (-43.7939, -27.066) -> (-82.0711, 27.066)
  line L2 (-124, 27.066) -> (-43.7939, -27.066)
  line L3 (-82.0711, 27.066) -> (-124, 27.066)
  line L4 (-59.6927, -11.51) -> (-84.1416, 23.066)
  line L5 (-110.9231, 23.066) -> (-59.6927, -11.51)
  line L6 (-84.1416, 23.066) -> (-110.9231, 23.066)
  point P1 (0, 0)
  point P2 (-82.0711, 27.066)
  point P3 (-43.7939, -27.066)
  point P4 (-124, 27.066)
  dimension "d360" distance P1 P2 = 82.0711 (= "Linear Dimension-2")
  dimension "d361" distance P1 P2 = 27.066 (= "Linear Dimension-3")
  dimension "d362" distance P1 P3 = 43.7939 (= "Linear Dimension-4")
  dimension "d363" distance P1 P3 = 27.066 (= "Linear Dimension-5")
  dimension "d364" distance P1 P4 = 124 (= "Linear Dimension-6")
  dimension "d365" distance P1 P4 = 27.066 (= "Linear Dimension-7")
  dimension "d366" = 4 (= "memberWidth / 2")
extrude "Extrude3" cut sketch "B Facet 45 Triangle 1" profile of L5 L6 L4 against normal blind 4.7 (magnitude of "-( wall + 0.2 mm )")
sketch "B Facet 45 Triangle 2" plane through (0, 53.033, 53.033) normal (0, 0.7071, 0.7071) x axis (1, 0, 0)
  line L1 (-124, 27.066) -> (-43.7939, -27.066)
  line L2 (-124, -27.066) -> (-124, 27.066)
  line L3 (-43.7939, -27.066) -> (-124, -27.066)
  line L4 (-120, 19.5406) -> (-56.8709, -23.066)
  line L5 (-120, -23.066) -> (-120, 19.5406)
  line L6 (-56.8709, -23.066) -> (-120, -23.066)
  point P1 (0, 0)
  point P2 (-43.7939, -27.066)
  point P3 (-124, 27.066)
  point P4 (-124, -27.066)
  dimension "d369" distance P1 P2 = 43.7939 (= "Linear Dimension-2")
  dimension "d370" distance P1 P2 = 27.066 (= "Linear Dimension-3")
  dimension "d371" distance P1 P3 = 124 (= "Linear Dimension-4")
  dimension "d372" distance P1 P3 = 27.066 (= "Linear Dimension-5")
  dimension "d373" distance P1 P4 = 124 (= "Linear Dimension-6")
  dimension "d374" distance P1 P4 = 27.066 (= "Linear Dimension-7")
  dimension "d375" = -4 (= "-memberWidth / 2")
extrude "Extrude4" cut sketch "B Facet 45 Triangle 2" profile of L5 L6 L4 against normal blind 4.7 (magnitude of "-( wall + 0.2 mm )")
fillet "Fillet2" radius 1.5 (= "apertureRadius")
work_plane "WorkPlane5" RotateAngle 0 ExtraOffset 0
work_plane "WorkPlane6" AlongDistance 75 (= "bodyWidth / 2") ExtraOffset 0
sketch "B Facet 90 Triangle 1" plane through (0, 0, 75) normal (0, 0, 1) x axis (1, 0, 0)
  line L1 (-36.9655, 27.066) -> (17.1665, -27.066)
  line L2 (-53.4167, -27.066) -> (-36.9655, 27.066)
  line L3 (17.1665, -27.066) -> (-53.4167, -27.066)
  line L4 (-35.0777, 19.5214) -> (7.5097, -23.066)
  line L5 (-48.0205, -23.066) -> (-35.0777, 19.5214)
  line L6 (7.5097, -23.066) -> (-48.0205, -23.066)
  point P1 (0, 0)
  point P2 (17.1665, -27.066)
  point P3 (-36.9655, 27.066)
  point P4 (-53.4167, -27.066)
  dimension "d384" distance P1 P2 = 17.1665 (= "Linear Dimension-2")
  dimension "d385" distance P1 P2 = 27.066 (= "Linear Dimension-3")
  dimension "d386" distance P1 P3 = 36.9655 (= "Linear Dimension-4")
  dimension "d387" distance P1 P3 = 27.066 (= "Linear Dimension-5")
  dimension "d388" distance P1 P4 = 53.4167 (= "Linear Dimension-6")
  dimension "d389" distance P1 P4 = 27.066 (= "Linear Dimension-7")
  dimension "d390" = -4 (= "-memberWidth / 2")
extrude "Extrude5" cut sketch "B Facet 90 Triangle 1" profile of L5 L6 L4 against normal blind 4.7 (magnitude of "-( wall + 0.2 mm )")
sketch "B Facet 90 Triangle 2" plane through (0, 0, 75) normal (0, 0, 1) x axis (1, 0, 0)
  line L1 (-53.4167, -27.066) -> (-36.9655, 27.066)
  line L2 (-124, 27.066) -> (-53.4167, -27.066)
  line L3 (-36.9655, 27.066) -> (-124, 27.066)
  line L4 (-55.5648, -20.3777) -> (-42.3618, 23.066)
  line L5 (-112.2115, 23.066) -> (-55.5648, -20.3777)
  line L6 (-42.3618, 23.066) -> (-112.2115, 23.066)
  point P1 (0, 0)
  point P2 (-36.9655, 27.066)
  point P3 (-53.4167, -27.066)
  point P4 (-124, 27.066)
  dimension "d393" distance P1 P2 = 36.9655 (= "Linear Dimension-2")
  dimension "d394" distance P1 P2 = 27.066 (= "Linear Dimension-3")
  dimension "d395" distance P1 P3 = 53.4167 (= "Linear Dimension-4")
  dimension "d396" distance P1 P3 = 27.066 (= "Linear Dimension-5")
  dimension "d397" distance P1 P4 = 124 (= "Linear Dimension-6")
  dimension "d398" distance P1 P4 = 27.066 (= "Linear Dimension-7")
  dimension "d399" = 4 (= "memberWidth / 2")
extrude "Extrude6" cut sketch "B Facet 90 Triangle 2" profile of L5 L6 L4 against normal blind 4.7 (magnitude of "-( wall + 0.2 mm )")
sketch "B Facet 90 Triangle 3" plane through (0, 0, 75) normal (0, 0, 1) x axis (1, 0, 0)
  line L1 (-124, 27.066) -> (-53.4167, -27.066)
  line L2 (-124, -27.066) -> (-124, 27.066)
  line L3 (-53.4167, -27.066) -> (-124, -27.066)
  line L4 (-120, 18.9574) -> (-65.2053, -23.066)
  line L5 (-120, -23.066) -> (-120, 18.9574)
  line L6 (-65.2053, -23.066) -> (-120, -23.066)
  point P1 (0, 0)
  point P2 (-53.4167, -27.066)
  point P3 (-124, 27.066)
  point P4 (-124, -27.066)
  dimension "d402" distance P1 P2 = 53.4167 (= "Linear Dimension-2")
  dimension "d403" distance P1 P2 = 27.066 (= "Linear Dimension-3")
  dimension "d404" distance P1 P3 = 124 (= "Linear Dimension-4")
  dimension "d405" distance P1 P3 = 27.066 (= "Linear Dimension-5")
  dimension "d406" distance P1 P4 = 124 (= "Linear Dimension-6")
  dimension "d407" distance P1 P4 = 27.066 (= "Linear Dimension-7")
  dimension "d408" = -4 (= "-memberWidth / 2")
extrude "Extrude7" cut sketch "B Facet 90 Triangle 3" profile of L5 L6 L4 against normal blind 4.7 (magnitude of "-( wall + 0.2 mm )")
fillet "Fillet3" radius 1.5 (= "apertureRadius")
work_plane "WorkPlane7" RotateAngle 45 ExtraOffset 0
work_plane "WorkPlane8" AlongDistance 75 (= "bodyWidth / 2") ExtraOffset 0
sketch "B Facet 135 Triangle 1" plane through (0, -53.033, 53.033) normal (0, -0.7071, 0.7071) x axis (1, 0, 0)
  line L1 (62.2721, -27.066) -> (23.9949, 27.066)
  line L2 (-25.3367, 27.066) -> (62.2721, -27.066)
  line L3 (23.9949, 27.066) -> (-25.3367, 27.066)
  line L4 (47.6674, -13.34) -> (21.9244, 23.066)
  line L5 (-11.2532, 23.066) -> (47.6674, -13.34)
  line L6 (21.9244, 23.066) -> (-11.2532, 23.066)
  point P1 (0, 0)
  point P2 (23.9949, 27.066)
  point P3 (62.2721, -27.066)
  point P4 (-25.3367, 27.066)
  dimension "d417" distance P1 P2 = 23.9949 (= "Linear Dimension-2")
  dimension "d418" distance P1 P2 = 27.066 (= "Linear Dimension-3")
  dimension "d419" distance P1 P3 = 62.2721 (= "Linear Dimension-4")
  dimension "d420" distance P1 P3 = 27.066 (= "Linear Dimension-5")
  dimension "d421" distance P1 P4 = 25.3367 (= "Linear Dimension-6")
  dimension "d422" distance P1 P4 = 27.066 (= "Linear Dimension-7")
  dimension "d423" = 4 (= "memberWidth / 2")
extrude "Extrude8" cut sketch "B Facet 135 Triangle 1" profile of L5 L6 L4 against normal blind 4.7 (magnitude of "-( wall + 0.2 mm )")
sketch "B Facet 135 Triangle 2" plane through (0, -53.033, 53.033) normal (0, -0.7071, 0.7071) x axis (1, 0, 0)
  line L1 (-25.3367, 27.066) -> (62.2721, -27.066)
  line L2 (-61.9093, -27.066) -> (-25.3367, 27.066)
  line L3 (62.2721, -27.066) -> (-61.9093, -27.066)
  line L4 (-24.1722, 21.6445) -> (48.1886, -23.066)
  line L5 (-54.3795, -23.066) -> (-24.1722, 21.6445)
  line L6 (48.1886, -23.066) -> (-54.3795, -23.066)
  point P1 (0, 0)
  point P2 (62.2721, -27.066)
  point P3 (-25.3367, 27.066)
  point P4 (-61.9093, -27.066)
  dimension "d426" distance P1 P2 = 62.2721 (= "Linear Dimension-2")
  dimension "d427" distance P1 P2 = 27.066 (= "Linear Dimension-3")
  dimension "d428" distance P1 P3 = 25.3367 (= "Linear Dimension-4")
  dimension "d429" distance P1 P3 = 27.066 (= "Linear Dimension-5")
  dimension "d430" distance P1 P4 = 61.9093 (= "Linear Dimension-6")
  dimension "d431" distance P1 P4 = 27.066 (= "Linear Dimension-7")
  dimension "d432" = -4 (= "-memberWidth / 2")
extrude "Extrude9" cut sketch "B Facet 135 Triangle 2" profile of L5 L6 L4 against normal blind 4.7 (magnitude of "-( wall + 0.2 mm )")
sketch "B Facet 135 Triangle 3" plane through (0, -53.033, 53.033) normal (0, -0.7071, 0.7071) x axis (1, 0, 0)
  line L1 (-61.9093, -27.066) -> (-25.3367, 27.066)
  line L2 (-124, 27.066) -> (-61.9093, -27.066)
  line L3 (-25.3367, 27.066) -> (-124, 27.066)
  line L4 (-62.6909, -21.0779) -> (-32.8665, 23.066)
  line L5 (-113.325, 23.066) -> (-62.6909, -21.0779)
  line L6 (-32.8665, 23.066) -> (-113.325, 23.066)
  point P1 (0, 0)
  point P2 (-25.3367, 27.066)
  point P3 (-61.9093, -27.066)
  point P4 (-124, 27.066)
  dimension "d435" distance P1 P2 = 25.3367 (= "Linear Dimension-2")
  dimension "d436" distance P1 P2 = 27.066 (= "Linear Dimension-3")
  dimension "d437" distance P1 P3 = 61.9093 (= "Linear Dimension-4")
  dimension "d438" distance P1 P3 = 27.066 (= "Linear Dimension-5")
  dimension "d439" distance P1 P4 = 124 (= "Linear Dimension-6")
  dimension "d440" distance P1 P4 = 27.066 (= "Linear Dimension-7")
  dimension "d441" = 4 (= "memberWidth / 2")
extrude "Extrude10" cut sketch "B Facet 135 Triangle 3" profile of L5 L6 L4 against normal blind 4.7 (magnitude of "-( wall + 0.2 mm )")
sketch "B Facet 135 Triangle 4" plane through (0, -53.033, 53.033) normal (0, -0.7071, 0.7071) x axis (1, 0, 0)
  line L1 (-124, 27.066) -> (-61.9093, -27.066)
  line L2 (-124, -27.066) -> (-124, 27.066)
  line L3 (-61.9093, -27.066) -> (-124, -27.066)
  line L4 (-120, 18.272) -> (-72.5843, -23.066)
  line L5 (-120, -23.066) -> (-120, 18.272)
  line L6 (-72.5843, -23.066) -> (-120, -23.066)
  point P1 (0, 0)
  point P2 (-61.9093, -27.066)
  point P3 (-124, 27.066)
  point P4 (-124, -27.066)
  dimension "d444" distance P1 P2 = 61.9093 (= "Linear Dimension-2")
  dimension "d445" distance P1 P2 = 27.066 (= "Linear Dimension-3")
  dimension "d446" distance P1 P3 = 124 (= "Linear Dimension-4")
  dimension "d447" distance P1 P3 = 27.066 (= "Linear Dimension-5")
  dimension "d448" distance P1 P4 = 124 (= "Linear Dimension-6")
  dimension "d449" distance P1 P4 = 27.066 (= "Linear Dimension-7")
  dimension "d450" = -4 (= "-memberWidth / 2")
extrude "Extrude11" cut sketch "B Facet 135 Triangle 4" profile of L5 L6 L4 against normal blind 4.7 (magnitude of "-( wall + 0.2 mm )")
fillet "Fillet4" radius 1.5 (= "apertureRadius")
work_plane "WorkPlane9" RotateAngle 90 ExtraOffset 0
work_plane "WorkPlane10" AlongDistance 75 (= "bodyWidth / 2") ExtraOffset 0
sketch "B Facet 180 Triangle 1" plane through (0, -75, 0) normal (0, -1, 0) x axis (-1, 0, 0)
  line L1 (-65.1005, 27.066) -> (-65.1005, -27.066)
  line L2 (-2.067, -27.066) -> (-65.1005, 27.066)
  line L3 (-65.1005, -27.066) -> (-2.067, -27.066)
  line L4 (-61.1005, 18.3583) -> (-61.1005, -23.066)
  line L5 (-12.8644, -23.066) -> (-61.1005, 18.3583)
  line L6 (-61.1005, -23.066) -> (-12.8644, -23.066)
  point P1 (0, 0)
  point P2 (-65.1005, -27.066)
  point P3 (-65.1005, 27.066)
  point P4 (-2.067, -27.066)
  dimension "d459" distance P1 P2 = 65.1005 (= "Linear Dimension-2")
  dimension "d460" distance P1 P2 = 27.066 (= "Linear Dimension-3")
  dimension "d461" distance P1 P3 = 65.1005 (= "Linear Dimension-4")
  dimension "d462" distance P1 P3 = 27.066 (= "Linear Dimension-5")
  dimension "d463" distance P1 P4 = 2.067 (= "Linear Dimension-6")
  dimension "d464" distance P1 P4 = 27.066 (= "Linear Dimension-7")
  dimension "d465" = 4 (= "memberWidth / 2")
extrude "Extrude12" cut sketch "B Facet 180 Triangle 1" profile of L5 L6 L4 against normal blind 4.7 (magnitude of "-( wall + 0.2 mm )")
sketch "B Facet 180 Triangle 2" plane through (0, -75, 0) normal (0, -1, 0) x axis (-1, 0, 0)
  line L1 (-2.067, -27.066) -> (-65.1005, 27.066)
  line L2 (60.9665, 27.066) -> (-2.067, -27.066)
  line L3 (-65.1005, 27.066) -> (60.9665, 27.066)
  line L4 (-2.067, -21.7934) -> (-54.3031, 23.066)
  line L5 (50.1691, 23.066) -> (-2.067, -21.7934)
  line L6 (-54.3031, 23.066) -> (50.1691, 23.066)
  point P1 (0, 0)
  point P2 (-65.1005, 27.066)
  point P3 (-2.067, -27.066)
  point P4 (60.9665, 27.066)
  dimension "d468" distance P1 P2 = 65.1005 (= "Linear Dimension-2")
  dimension "d469" distance P1 P2 = 27.066 (= "Linear Dimension-3")
  dimension "d470" distance P1 P3 = 2.067 (= "Linear Dimension-4")
  dimension "d471" distance P1 P3 = 27.066 (= "Linear Dimension-5")
  dimension "d472" distance P1 P4 = 60.9665 (= "Linear Dimension-6")
  dimension "d473" distance P1 P4 = 27.066 (= "Linear Dimension-7")
  dimension "d474" = -4 (= "-memberWidth / 2")
extrude "Extrude13" cut sketch "B Facet 180 Triangle 2" profile of L5 L6 L4 against normal blind 4.7 (magnitude of "-( wall + 0.2 mm )")
sketch "B Facet 180 Triangle 3" plane through (0, -75, 0) normal (0, -1, 0) x axis (-1, 0, 0)
  line L1 (60.9665, 27.066) -> (-2.067, -27.066)
  line L2 (124, -27.066) -> (60.9665, 27.066)
  line L3 (-2.067, -27.066) -> (124, -27.066)
  line L4 (60.9665, 21.7934) -> (8.7304, -23.066)
  line L5 (113.2026, -23.066) -> (60.9665, 21.7934)
  line L6 (8.7304, -23.066) -> (113.2026, -23.066)
  point P1 (0, 0)
  point P2 (-2.067, -27.066)
  point P3 (60.9665, 27.066)
  point P4 (124, -27.066)
  dimension "d477" distance P1 P2 = 2.067 (= "Linear Dimension-2")
  dimension "d478" distance P1 P2 = 27.066 (= "Linear Dimension-3")
  dimension "d479" distance P1 P3 = 60.9665 (= "Linear Dimension-4")
  dimension "d480" distance P1 P3 = 27.066 (= "Linear Dimension-5")
  dimension "d481" distance P1 P4 = 124 (= "Linear Dimension-6")
  dimension "d482" distance P1 P4 = 27.066 (= "Linear Dimension-7")
  dimension "d483" = 4 (= "memberWidth / 2")
extrude "Extrude14" cut sketch "B Facet 180 Triangle 3" profile of L5 L6 L4 against normal blind 4.7 (magnitude of "-( wall + 0.2 mm )")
